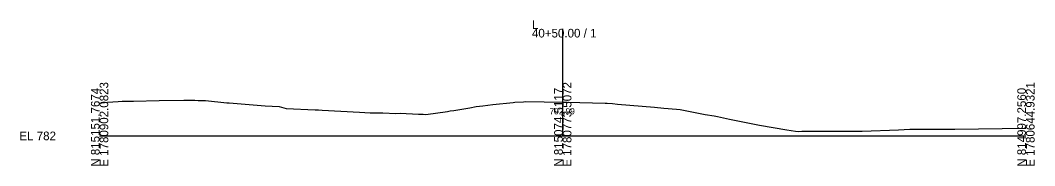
# Model space of a CAD drawing. Extents: x -26 to 7903, y -10 to 9573.
# Drawn here: x 974.3 to 1302.8, y 1490.3 to 1537.6 of the extents above; entities that cross this region are included whole.
import ezdxf

# ---------------------------------------------------------------- set-up
doc = ezdxf.new("R2010")
doc.units = 0
for name, color, linetype in [('Exist Cross Section Cell', 7, 'Continuous'), ('Exist XS Center Line Elevation Label', 7, 'Continuous'), ('Exist XS Ground Line', 7, 'Continuous')]:
    doc.layers.add(name, color=color, linetype=linetype)

msp = doc.modelspace()

# ---------------------------------------------------------------- linework, layer by layer
at = {"layer": 'Exist Cross Section Cell'}
for p, q in [((1150, 1500), (1150, 1534.76)), ((1000, 1500), (1150, 1500)), ((1150, 1500), (1300, 1500))]:
    msp.add_line(p, q, dxfattribs=at)
at = {"layer": 'Exist XS Ground Line'}
for p, q in [((1007.34, 1511.23), (1010.92, 1511.3)), ((1010.92, 1511.3), (1019.32, 1511.48)), ((1019.32, 1511.48), (1027.26, 1511.56)), ((1027.26, 1511.56), (1030.85, 1511.59)), ((1030.85, 1511.59), (1031.91, 1511.55)), ((1031.91, 1511.55), (1034.26, 1511.46)), ((1034.26, 1511.46), (1041.19, 1510.76)), ((1000, 1510.63), (1000.73, 1510.78)), ((1000.73, 1510.78), (1002.55, 1511)), ((1002.55, 1511), (1005.99, 1511.17)), ((1005.99, 1511.17), (1007.34, 1511.23)), ((1041.19, 1510.76), (1041.94, 1510.69)), ((1041.94, 1510.69), (1053.57, 1509.79)), ((1053.57, 1509.79), (1058.14, 1509.57)), ((1058.14, 1509.57), (1058.93, 1509.34)), ((1058.93, 1509.34), (1060.43, 1508.93)), ((1060.43, 1508.93), (1069.84, 1508.52)), ((1069.84, 1508.52), (1070.87, 1508.47)), ((1070.87, 1508.47), (1072.12, 1508.41)), ((1072.12, 1508.41), (1084.19, 1507.75)), ((1105.62, 1506.99), (1112.63, 1507.97)), ((1112.63, 1507.97), (1113.54, 1508.09)), ((1113.54, 1508.09), (1114.71, 1508.26)), ((1114.71, 1508.26), (1119.86, 1509.17)), ((1119.86, 1509.17), (1122, 1509.59)), ((1122, 1509.59), (1124.12, 1509.8)), ((1124.12, 1509.8), (1127.31, 1510.16)), ((1127.31, 1510.16), (1133.93, 1510.87)), ((1133.93, 1510.87), (1134.49, 1510.93)), ((1134.49, 1510.93), (1137.3, 1511.1)), ((1137.3, 1511.1), (1137.93, 1511.13)), ((1137.93, 1511.13), (1150, 1510.99)), ((1150, 1510.99), (1151.03, 1510.97)), ((1151.03, 1510.97), (1151.42, 1510.96)), ((1151.42, 1510.96), (1163.71, 1510.67)), ((1163.71, 1510.67), (1164.36, 1510.63)), ((1164.36, 1510.63), (1166.08, 1510.51)), ((1166.08, 1510.51), (1167.73, 1510.33)), ((1167.73, 1510.33), (1179.72, 1509.28)), ((1179.72, 1509.28), (1182.72, 1509.01)), ((1182.72, 1509.01), (1186.85, 1508.68)), ((1186.85, 1508.68), (1187.99, 1508.6)), ((1187.99, 1508.6), (1195.03, 1507.18)), ((1084.19, 1507.75), (1087.66, 1507.5)), ((1087.66, 1507.5), (1091.7, 1507.47)), ((1091.7, 1507.47), (1095.98, 1507.25)), ((1095.98, 1507.25), (1097.3, 1507.36)), ((1097.3, 1507.36), (1103.32, 1507.06)), ((1103.32, 1507.06), (1104.75, 1507.01)), ((1104.75, 1507.01), (1105.62, 1506.99)), ((1195.03, 1507.18), (1196.09, 1507)), ((1196.09, 1507), (1199.02, 1506.48)), ((1199.02, 1506.48), (1200.09, 1506.26)), ((1200.09, 1506.26), (1203.95, 1505.49)), ((1203.95, 1505.49), (1213.75, 1503.49)), ((1213.75, 1503.49), (1222.51, 1502.01)), ((1222.51, 1502.01), (1225.41, 1501.51)), ((1225.41, 1501.51), (1226.2, 1501.48)), ((1226.2, 1501.48), (1227.46, 1501.5)), ((1227.46, 1501.5), (1246.94, 1501.52)), ((1246.94, 1501.52), (1258.75, 1501.99)), ((1258.75, 1501.99), (1262.35, 1502.17)), ((1262.35, 1502.17), (1271.32, 1502.23)), ((1271.32, 1502.23), (1273.51, 1502.17)), ((1273.51, 1502.17), (1277, 1502.23)), ((1277, 1502.23), (1300, 1502.47))]:
    msp.add_line(p, q, dxfattribs=at)

# ---------------------------------------------------------------- texts
at = {"layer": 'Exist Cross Section Cell'}
for s, p in [('L', (1140, 1534.76)), ('40+50.00 / 1', (1140, 1531.96)), ('EL 782', (974, 1498.6))]:
    msp.add_text(s, height=2.8, dxfattribs=at).set_placement(p)
for s, p in [('N 815151.7674', (1000, 1490)), ('E 1780902.0823', (1002.8, 1490)), ('N 815074.5117', (1150, 1490)), ('E 1780773.5072', (1152.8, 1490)), ('N 814997.2560', (1300, 1490)), ('E 1780644.9321', (1302.8, 1490))]:
    msp.add_text(s, height=2.8, rotation=90, dxfattribs=at).set_placement(p)
at = {"layer": 'Exist XS Center Line Elevation Label'}
msp.add_text('792.99', height=2, dxfattribs=at).set_placement((1145.73, 1506.99))

doc.saveas('drawing.dxf')
